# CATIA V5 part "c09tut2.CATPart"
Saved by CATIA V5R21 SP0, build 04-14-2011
Part number: Part1
Bounding box of the stored display mesh (mm): x -163 to 90, y -77.362 to 77.362, z -85 to 85
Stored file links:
  D:\CATIA V5R21 E-RESOURCES\CATIA-V5R21\catia-v5r21-prt\c09-catia-v5r20-prt\c09-catia-v5r21-tut02.CATPart
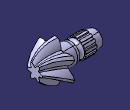
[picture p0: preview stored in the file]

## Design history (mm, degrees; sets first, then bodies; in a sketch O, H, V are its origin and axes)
Body1 (main body)
  Sketch1 on zx-plane, origin (0, 0, 0), H (-1, 0, 0), V (0, 0, 1)
    axis line L1 (-102.3376, 0) -> (234.6005, 0)
    point P1 (-102.3376, 0)
    line L2 (0, 0) -> (163, 0)
    line L3 (0, 0) -> (0, -45)
    line L4 (0, -45) -> (5, -45)
    line L5 (5, -45) -> (5, -39)
    line L6 (5, -39) -> (51, -39)
    line L7 (51, -39) -> (51, -38)
    line L8 (51, -38) -> (61, -38)
    point P10 (83, -36)
    line L9 (83, -36) -> (131, -36)
    line L10 (131, -36) -> (131, -32.5)
    line L11 (131, -32.5) -> (163, -32.5)
    line L12 (163, -32.5) -> (163, 0)
    line L13 (61, -38) -> (61, -36)
    point P14 (61, -36)
    arc A1 centre (72, -36) radius 11 from (83, -36) to (61, -36) ccw
    point P16 (61, -36)
    length L4 = 5
    "Radius" L11 L1 = 32.5
    "Radius" L4 L1 = 45
    "Radius" L6 L1 = 39
    "Radius" L8 L1 = 38
    "Radius" L9 L1 = 36
    length L6 = 46
    length L8 = 10
    length L9 = 48
    length L11 = 32
    radius A1 = 11
    distance L13 P10 = 22
    coincidence: P1 H, P16 P14
    horizontal: L1 H, L2 H, L4 H, L6 H, L8 H, L9 H, L11 H
    vertical: L3 V, L5 V, L7 V, L10 V, L12 V, L13 V
    tangency: L13 A1
  Shaft1: profile Sketch1, axis Sketch1.L1, angle 360
  Sketch2 on face of Shaft1 from Sketch1.L10, origin (-131, 0, 0), H (0, -1, 0), V (0, 0, 1)
    projected circle E1 centre (0, 0) radius 36 from edge [face of Shaft1 from Sketch1.L9 | face of Shaft1 from Sketch1.L10]
    projected arc E2 centre (0, 0) radius 36 from (5, 35.6511) to (-5, 35.6511) ccw from edge [face of Shaft1 from Sketch1.L9 | face of Shaft1 from Sketch1.L10]
    line L1 (-5, 35.6511) -> (-5, 40.6511)
    point P1 (-5, 35.6511)
    line L2 (-5, 40.6511) -> (5, 40.6511)
    line L3 (5, 40.6511) -> (5, 35.6511)
    point P4 (5, 35.6511)
    point P5 (5, 35.6511)
    length L2 = 10
    distance L1 V = 5
    length L3 = 5
    coincidence: P1 E1, L3 P4, E1 P5, P4 P5
    vertical: L1 V, L3 V
    horizontal: L2 H
  Pad1: profile Sketch2, direction (1, 0, 0), length 48
  CircPattern1: of Pad1, instances 13, angular step 27.6923 {= 360.0*1 deg/CircPattern1.AngularNumber}, axis from face of Shaft1 from Sketch1.L9
  Sketch3 on face of Shaft1 from Sketch1.L3, origin (0, 0, 0), H (0, 1, 0), V (0, 0, 1)
    arc A1 centre (0, 0) radius 50 from (-49.6863, 5.5924) to (-49.6863, -5.5924) ccw
    line L1 (-7.5, 85) -> (7.5, 85)
    point P1 (-7.5, 85)
    arc A2 centre (44.9945, 46.6682) radius 65 from (-7.5, 85) to (-20, 45.8258) ccw
    point P4 (-20, 45.8258)
    arc A3 centre (-44.9945, 46.6682) radius 65 from (20, 45.8258) to (7.5, 85) ccw
    point P6 (20, 45.8258)
    arc A4 centre (-17.9186, 62.3005) radius 65 from (-77.3622, 36.0048) to (-49.6863, 5.5924) ccw
    line L2 (-77.3622, 36.0048) -> (-69.8622, 48.9952)
    arc A5 centre (-62.9132, -15.6323) radius 65 from (-29.6863, 40.2334) to (-69.8622, 48.9952) ccw
    arc A6 centre (-62.9132, 15.6323) radius 65 from (-69.8622, -48.9952) to (-29.6863, -40.2334) ccw
    line L3 (-69.8622, -48.9952) -> (-77.3622, -36.0048)
    arc A7 centre (-17.9186, -62.3005) radius 65 from (-49.6863, -5.5924) to (-77.3622, -36.0048) ccw
    arc A8 centre (-44.9945, -46.6682) radius 65 from (7.5, -85) to (20, -45.8258) ccw
    line L4 (7.5, -85) -> (-7.5, -85)
    arc A9 centre (44.9945, -46.6682) radius 65 from (-20, -45.8258) to (-7.5, -85) ccw
    arc A10 centre (17.9186, -62.3005) radius 65 from (77.3622, -36.0048) to (49.6863, -5.5924) ccw
    line L5 (77.3622, -36.0048) -> (69.8622, -48.9952)
    arc A11 centre (62.9132, 15.6323) radius 65 from (29.6863, -40.2334) to (69.8622, -48.9952) ccw
    arc A12 centre (62.9132, -15.6323) radius 65 from (69.8622, 48.9952) to (29.6863, 40.2334) ccw
    line L6 (69.8622, 48.9952) -> (77.3622, 36.0048)
    arc A13 centre (17.9186, 62.3005) radius 65 from (49.6863, 5.5924) to (77.3622, 36.0048) ccw
    arc A14 centre (0, 0) radius 50 from (-29.6863, -40.2334) to (-20, -45.8258) ccw
    arc A15 centre (0, 0) radius 50 from (20, -45.8258) to (29.6863, -40.2334) ccw
    arc A16 centre (0, 0) radius 50 from (49.6863, -5.5924) to (49.6863, 5.5924) ccw
    arc A17 centre (0, 0) radius 50 from (29.6863, 40.2334) to (20, 45.8258) ccw
    arc A18 centre (0, 0) radius 50 from (-20, 45.8258) to (-29.6863, 40.2334) ccw
    radius A1 = 50
    length L1 = 15
    distance H L1 = 85
    distance V P1 = 7.5
    distance V P4 = 20
    distance P4 P6 H = 40
    radius A2 = 65
    radius A3 = 65
    horizontal: L1 H
    coincidence: A1 P4, A1 P6, A1 A14, A14 A15, A15 A16, A16 A17, A17 A18
  Plane1: type Offset, RefPlane face of Shaft1 from Sketch1.L3, Offset 45, reversed
  Sketch4 on Plane1, origin (45, 0, 0), H (0, -1, 0), V (0, 0, 1)
    arc A1 centre (0.0494, -0.0379) radius 37.5335 from (-29.2904, -23.446) to (-23.3588, -29.3776) ccw
    arc A2 centre (-42.517, 23.4762) radius 48.7508 from (-60.0964, -21.9947) to (-29.2904, -23.446) ccw
    line L1 (-60.0964, -21.9947) -> (-63.0081, -11.1281)
    arc A3 centre (-25.0485, -41.7174) radius 48.7508 from (-37.0549, 5.5318) to (-63.0081, -11.1281) ccw
    arc A4 centre (0.0581, -0.0704) radius 37.5335 from (-34.8838, 13.6345) to (-37.0549, 5.5318) ccw
    arc A5 centre (-0.8613, 48.5502) radius 48.7508 from (-49.03, 41.0389) to (-34.8838, 13.6345) ccw
    line L2 (-49.03, 41.0389) -> (-41.075, 48.9938)
    arc A6 centre (-48.5863, 0.8252) radius 48.7508 from (-13.6706, 34.8477) to (-41.075, 48.9938) ccw
    arc A7 centre (0.0343, -0.0942) radius 37.5335 from (-5.5679, 37.0188) to (-13.6706, 34.8477) ccw
    arc A8 centre (41.6812, 25.0123) radius 48.7508 from (11.0919, 62.9719) to (-5.5679, 37.0188) ccw
    line L3 (11.0919, 62.9719) -> (21.9586, 60.0602)
    arc A9 centre (-23.5123, 42.4809) radius 48.7508 from (23.4099, 29.2542) to (21.9586, 60.0602) ccw
    arc A10 centre (0.0017, -0.0855) radius 37.5335 from (29.3415, 23.3226) to (23.4099, 29.2542) ccw
    arc A11 centre (42.5681, -23.5996) radius 48.7508 from (60.1475, 21.8713) to (29.3415, 23.3226) ccw
    line L4 (60.1475, 21.8713) -> (63.0592, 11.0047)
    arc A12 centre (25.0996, 41.594) radius 48.7508 from (37.1061, -5.6552) to (63.0592, 11.0047) ccw
    arc A13 centre (-0.007, -0.053) radius 37.5335 from (34.9349, -13.7579) to (37.1061, -5.6552) ccw
    arc A14 centre (0.9125, -48.6736) radius 48.7508 from (49.0811, -41.1623) to (34.9349, -13.7579) ccw
    line L5 (49.0811, -41.1623) -> (41.1261, -49.1172)
    arc A15 centre (48.6375, -0.9486) radius 48.7508 from (13.7217, -34.9711) to (41.1261, -49.1172) ccw
    arc A16 centre (0.0168, -0.0292) radius 37.5335 from (5.619, -37.1422) to (13.7217, -34.9711) ccw
    arc A17 centre (-41.6301, -25.1357) radius 48.7508 from (-11.0408, -63.0953) to (5.619, -37.1422) ccw
    line L6 (-11.0408, -63.0953) -> (-21.9075, -60.1836)
    arc A18 centre (23.5634, -42.6043) radius 48.7508 from (-23.3588, -29.3776) to (-21.9075, -60.1836) ccw
  Plane2: type Offset, RefPlane face of Shaft1 from Sketch1.L3, Offset 90, reversed
  Sketch5 on Plane2, origin (90, 0, 0), H (0, -1, 0), V (0, 0, 1)
    arc A1 centre (-0.0292, -0.0168) radius 18.7835 from (17.1847, 7.5) to (15.0875, 11.1324) ccw
    arc A2 centre (-5.8629, 23.5926) radius 24.3758 from (15.0875, 11.1324) to (18.3732, 26.1983) ccw
    line L1 (18.3732, 26.1983) -> (13.5018, 29.0108)
    arc A3 centre (23.3632, 6.7189) radius 24.3758 from (13.5018, 29.0108) to (2.0971, 18.6324) ccw
    arc A4 centre (0, -0.0337) radius 18.7835 from (2.0971, 18.6324) to (-2.0971, 18.6324) ccw
    arc A5 centre (-23.3632, 6.7189) radius 24.3758 from (-2.0971, 18.6324) to (-13.5018, 29.0108) ccw
    line L2 (-13.5018, 29.0108) -> (-18.3732, 26.1983)
    arc A6 centre (5.8629, 23.5926) radius 24.3758 from (-18.3732, 26.1983) to (-15.0875, 11.1324) ccw
    arc A7 centre (0.0292, -0.0168) radius 18.7835 from (-15.0875, 11.1324) to (-17.1847, 7.5) ccw
    arc A8 centre (-17.5003, -16.8737) radius 24.3758 from (-17.1847, 7.5) to (-31.875, 2.8125) ccw
    line L3 (-31.875, 2.8125) -> (-31.875, -2.8125)
    arc A9 centre (-17.5003, 16.8737) radius 24.3758 from (-31.875, -2.8125) to (-17.1847, -7.5) ccw
    arc A10 centre (0.0292, 0.0168) radius 18.7835 from (-17.1847, -7.5) to (-15.0875, -11.1324) ccw
    arc A11 centre (5.8629, -23.5926) radius 24.3758 from (-15.0875, -11.1324) to (-18.3732, -26.1983) ccw
    line L4 (-18.3732, -26.1983) -> (-13.5018, -29.0108)
    arc A12 centre (-23.3632, -6.7189) radius 24.3758 from (-13.5018, -29.0108) to (-2.0971, -18.6324) ccw
    arc A13 centre (0, 0.0337) radius 18.7835 from (-2.0971, -18.6324) to (2.0971, -18.6324) ccw
    arc A14 centre (23.3632, -6.7189) radius 24.3758 from (2.0971, -18.6324) to (13.5018, -29.0108) ccw
    line L5 (13.5018, -29.0108) -> (18.3732, -26.1983)
    arc A15 centre (-5.8629, -23.5926) radius 24.3758 from (18.3732, -26.1983) to (15.0875, -11.1324) ccw
    arc A16 centre (-0.0292, 0.0168) radius 18.7835 from (15.0875, -11.1324) to (17.1847, -7.5) ccw
    arc A17 centre (17.5003, 16.8737) radius 24.3758 from (17.1847, -7.5) to (31.875, -2.8125) ccw
    line L6 (31.875, -2.8125) -> (31.875, 2.8125)
    arc A18 centre (17.5003, -16.8737) radius 24.3758 from (31.875, 2.8125) to (17.1847, 7.5) ccw
  Loft1: solid, Sections (Sketch3; Sketch4; Sketch5)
